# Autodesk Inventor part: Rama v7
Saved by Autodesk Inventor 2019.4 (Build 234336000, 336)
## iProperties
Created: 2020-01
Part Number: Rama v7
Material: Generic
Document SubType Name: Modeling
Designer: Administrator
Density: 1 g/cm^3
Appearance: Default
Author: Administrator
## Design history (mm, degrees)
feature "Body1"
body "Solid1"
